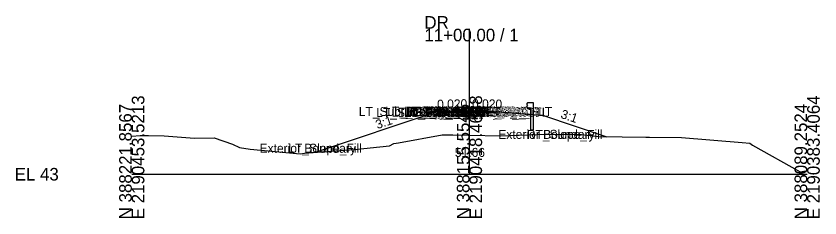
# Model space of a CAD drawing. Extents: x -26 to 153, y -10 to 1035.
# Drawn here: x -25.7 to 152.8, y 990.3 to 1035.1 of the extents above; entities that cross this region are included whole.
import ezdxf

# ---------------------------------------------------------------- set-up
doc = ezdxf.new("R2010")
doc.units = 0
for name, color, linetype in [('Default', 7, 'Continuous'), ('Exist CMT Ground Line', 7, 'Continuous'), ('Exist Cross Section Cell', 7, 'Continuous'), ('Exist XS Center Line Elevation Label', 7, 'Continuous'), ('Prop CMT Guardrail Graphics', 7, 'Continuous'), ('Prop CMT Pvmt Course 1', 7, 'Continuous'), ('Prop CMT Pvmt Course 2', 7, 'Continuous'), ('Prop CMT Pvmt Surface', 7, 'Continuous'), ('Prop CMT Shld Paved Course 1', 7, 'Continuous'), ('Prop CMT Shld Paved Course 2', 7, 'Continuous'), ('Prop CMT Slope Grass', 7, 'Continuous'), ('Prop CMT Subgrade Earthwork', 7, 'Continuous'), ('Prop XS SE Text', 7, 'Continuous'), ('Prop XS Side Slope Text', 7, 'Continuous'), ('Scratch_Level_1', 7, 'Continuous')]:
    doc.layers.add(name, color=color, linetype=linetype)

msp = doc.modelspace()

# ---------------------------------------------------------------- linework, layer by layer
at = {"layer": 'Exist CMT Ground Line'}
for p, q in [((59.21, 1006.95), (68.93, 1008.76)), ((68.93, 1008.76), (71.32, 1008.72)), ((71.32, 1008.72), (75, 1008.66)), ((81.9, 1008.55), (92.19, 1008.88)), ((92.19, 1008.88), (92.79, 1008.9)), ((92.79, 1008.9), (99.91, 1008.78)), ((99.91, 1008.78), (103.67, 1008.35)), ((0, 1008.42), (1.85, 1008.59)), ((1.85, 1008.59), (3.71, 1008.61)), ((3.71, 1008.61), (7.21, 1008.54)), ((7.21, 1008.54), (11.02, 1008.19)), ((11.02, 1008.19), (13.96, 1007.98)), ((13.96, 1007.98), (18.29, 1008.07)), ((18.29, 1008.07), (22.34, 1006.65)), ((58.24, 1006.79), (59.21, 1006.95)), ((75, 1008.66), (81.9, 1008.55)), ((103.67, 1008.35), (114.19, 1008.21)), ((114.19, 1008.21), (114.98, 1008.22)), ((114.98, 1008.22), (122.11, 1008.16)), ((122.11, 1008.16), (135.58, 1007)), ((135.58, 1007), (137.26, 1006.9)), ((22.34, 1006.65), (23.91, 1005.94)), ((23.91, 1005.94), (26.3, 1005.53)), ((26.3, 1005.53), (37.41, 1004.53)), ((41.26, 1004.9), (49.37, 1005.51)), ((49.37, 1005.51), (57.22, 1006.29)), ((57.22, 1006.29), (58.24, 1006.79)), ((137.26, 1006.9), (137.85, 1006.45)), ((137.85, 1006.45), (148.44, 1000.53)), ((37.41, 1004.53), (38.35, 1004.68)), ((38.35, 1004.68), (41.26, 1004.9)), ((148.44, 1000.53), (149.7, 1000.78)), ((149.7, 1000.78), (150, 1000.83))]:
    msp.add_line(p, q, dxfattribs=at)
at = {"layer": 'Exist Cross Section Cell'}
for p, q in [((75, 1000), (75, 1032.28)), ((0, 1000), (75, 1000)), ((75, 1000), (150, 1000))]:
    msp.add_line(p, q, dxfattribs=at)
at = {"layer": 'Prop CMT Guardrail Graphics'}
for points in [[(89.26, 1015.86), (87.92, 1015.86), (87.65, 1015.57)], [(89.26, 1009.86), (89.26, 1015.86)], [(87.65, 1015.57), (87.92, 1015.28)], [(87.92, 1015.28), (87.65, 1014.99)], [(87.65, 1014.99), (87.92, 1014.69), (88.59, 1014.69)], [(88.59, 1014.69), (88.59, 1009.86)], [(88.59, 1009.86), (89.26, 1009.86)]]:
    msp.add_lwpolyline(points, dxfattribs=at)
at = {"layer": 'Prop CMT Pvmt Course 1'}
for points in [[(75, 1014.05), (69.5, 1013.94)], [(69.5, 1013.93), (75, 1014.04)], [(69.5, 1013.94), (69.5, 1013.93)], [(75, 1014.04), (75, 1014.05)], [(75, 1014.05), (80.5, 1013.94)], [(75, 1014.04), (75, 1014.05)], [(80.5, 1013.93), (75, 1014.04)], [(80.5, 1013.94), (80.5, 1013.93)]]:
    msp.add_lwpolyline(points, dxfattribs=at)
msp.add_lwpolyline([(75, 1014.04), (75, 1013.92), (75, 1013.92), (75, 1014.04)], close=True, dxfattribs=at)
msp.add_lwpolyline([(75, 1014.04), (75, 1013.92), (75, 1013.92), (75, 1014.04)], close=True, dxfattribs=at)
at = {"layer": 'Prop CMT Pvmt Course 2'}
for points in [[(75, 1014.04), (69.5, 1013.93)], [(69.5, 1013.93), (69.5, 1013.68)], [(69.5, 1013.68), (75, 1013.79)], [(75, 1013.79), (75, 1014.04)], [(75, 1013.79), (75, 1014.04)], [(75, 1014.04), (80.5, 1013.93)], [(80.5, 1013.68), (75, 1013.79)], [(80.5, 1013.93), (80.5, 1013.68)]]:
    msp.add_lwpolyline(points, dxfattribs=at)
at = {"layer": 'Prop CMT Pvmt Surface'}
for points in [[(75, 1014.05), (69.5, 1013.94)], [(75, 1014.05), (80.5, 1013.94)]]:
    msp.add_lwpolyline(points, dxfattribs=at)
at = {"layer": 'Prop CMT Shld Paved Course 1'}
for points in [[(69.5, 1013.94), (69.49, 1013.93)], [(69.49, 1013.93), (69.5, 1013.93)], [(69.5, 1013.93), (69.5, 1013.94)], [(80.5, 1013.94), (80.51, 1013.93)], [(80.5, 1013.93), (80.5, 1013.94)], [(80.51, 1013.93), (80.5, 1013.93)]]:
    msp.add_lwpolyline(points, dxfattribs=at)
at = {"layer": 'Prop CMT Shld Paved Course 2'}
for points in [[(69.5, 1013.93), (69.49, 1013.93), (69.49, 1013.93), (69.23, 1013.67)], [(69.23, 1013.67), (69.5, 1013.68)], [(69.5, 1013.68), (69.5, 1013.93)], [(80.5, 1013.93), (80.51, 1013.93), (80.51, 1013.93), (80.77, 1013.67)], [(80.5, 1013.68), (80.5, 1013.93)], [(80.77, 1013.67), (80.5, 1013.68)]]:
    msp.add_lwpolyline(points, dxfattribs=at)
at = {"layer": 'Prop CMT Slope Grass'}
for p, q in [((67.5, 1013.78), (40.92, 1004.92)), ((69.5, 1013.94), (67.5, 1013.78)), ((80.5, 1013.94), (91.24, 1013.08)), ((91.24, 1013.08), (105.5, 1008.32))]:
    msp.add_line(p, q, dxfattribs=at)
at = {"layer": 'Prop CMT Subgrade Earthwork'}
for points in [[(69.5, 1013.68), (69.23, 1013.67), (69.01, 1013.9)], [(75, 1013.79), (69.5, 1013.68)], [(75, 1013.79), (80.5, 1013.68)], [(80.5, 1013.68), (80.77, 1013.67), (80.99, 1013.9)]]:
    msp.add_lwpolyline(points, dxfattribs=at)

# ---------------------------------------------------------------- texts
at = {"layer": 'Default'}
msp.add_text('-', height=0.0001, dxfattribs=at).set_placement((0, 1000))
at = {"layer": 'Exist Cross Section Cell'}
for s, p in [('DR', (65, 1032.28)), ('11+00.00 / 1', (65, 1029.48)), ('EL 43', (-26, 998.6))]:
    msp.add_text(s, height=2.8, dxfattribs=at).set_placement(p)
for s, p in [('E 2190453.5213', (2.8, 990)), ('E 2190418.4638', (77.8, 990)), ('E 2190383.4064', (152.8, 990)), ('N 388221.8567', (0, 990)), ('N 388155.5545', (75, 990)), ('N 388089.2524', (150, 990))]:
    msp.add_text(s, height=2.8, rotation=90, dxfattribs=at).set_placement(p)
at = {"layer": 'Exist XS Center Line Elevation Label'}
msp.add_text('51.66', height=2, dxfattribs=at).set_placement((71.76, 1003.84))
at = {"layer": 'Prop XS SE Text'}
for rotation, p in [(1.1458, (67.84, 1014.52)), (358.8542, (75.55, 1014.68))]:
    msp.add_text('0.020', height=2, rotation=rotation, dxfattribs=at).set_placement(p)
at = {"layer": 'Prop XS Side Slope Text'}
for rotation, p in [(341.5668, (95.11, 1012.52)), (18.4332, (54.55, 1009.99))]:
    msp.add_text('3:1', height=2, rotation=rotation, dxfattribs=at).set_placement(p)
at = {"layer": 'Scratch_Level_1'}
for s, p in [('LT_Sub_Trench_Out_DLT', (50.42, 1012.92)), ('LT_Sub_Trench_Out', (54.29, 1012.69)), ('LT_PS2_Shelf_Out', (56.32, 1012.95)), ('LT_GS_OS_CTL', (57.72, 1012.8)), ('LT_Sub_OEOT', (60.43, 1012.7)), ('LT_PV2_OEOT', (60.52, 1012.95)), ('LT_PS2_OEOP', (60.58, 1012.95)), ('LT_PV1_OEOT', (61.09, 1012.96)), ('RT_Sub_Trench_Out_DLT', (61.43, 1012.9)), ('RT_Sub_OEEOP', (64.17, 1012.79)), ('LT_Sub_OEEOP', (64.21, 1012.79)), ('RT_PV2_OEEOP', (64.26, 1013.04)), ('LT_PV2_OEEOP', (64.31, 1013.04)), ('RT_PV1_OEEOP', (64.83, 1012.92)), ('RT_Sub_Trench_Out', (64.84, 1012.68)), ('LT_PV1_OEEOP', (64.87, 1012.92)), ('RT_PV2_IEEOP', (64.91, 1013.04)), ('LT_PV2_IEEOP', (64.95, 1013.04)), ('RT_PV1_IEEOP', (65.47, 1012.92)), ('LT_PV1_IEEOP', (65.52, 1012.92)), ('RT_PS2_Shelf_Out', (66.37, 1012.93)), ('PV2_PGL', (68.91, 1013.04)), ('PV1_PGL', (69.47, 1013.05)), ('RT_Sub_OEOT', (70.45, 1012.68)), ('RT_PV2_OEOT', (70.55, 1012.93)), ('RT_PS2_OEOP', (70.62, 1012.93)), ('RT_PV1_OEOT', (71.11, 1012.94)), ('RT_GS_OS_CTL', (71.74, 1012.78)), ('Exterior Boundary', (81.4, 1007.84)), ('RT_Slope_Fill', (87.73, 1007.84)), ('Exterior Boundary', (28.38, 1004.76)), ('LT_Slope_Fill', (34.76, 1004.76))]:
    msp.add_text(s, height=2, dxfattribs=at).set_placement(p)

doc.saveas('drawing.dxf')
